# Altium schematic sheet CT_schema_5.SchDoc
size 300 x 177 mm
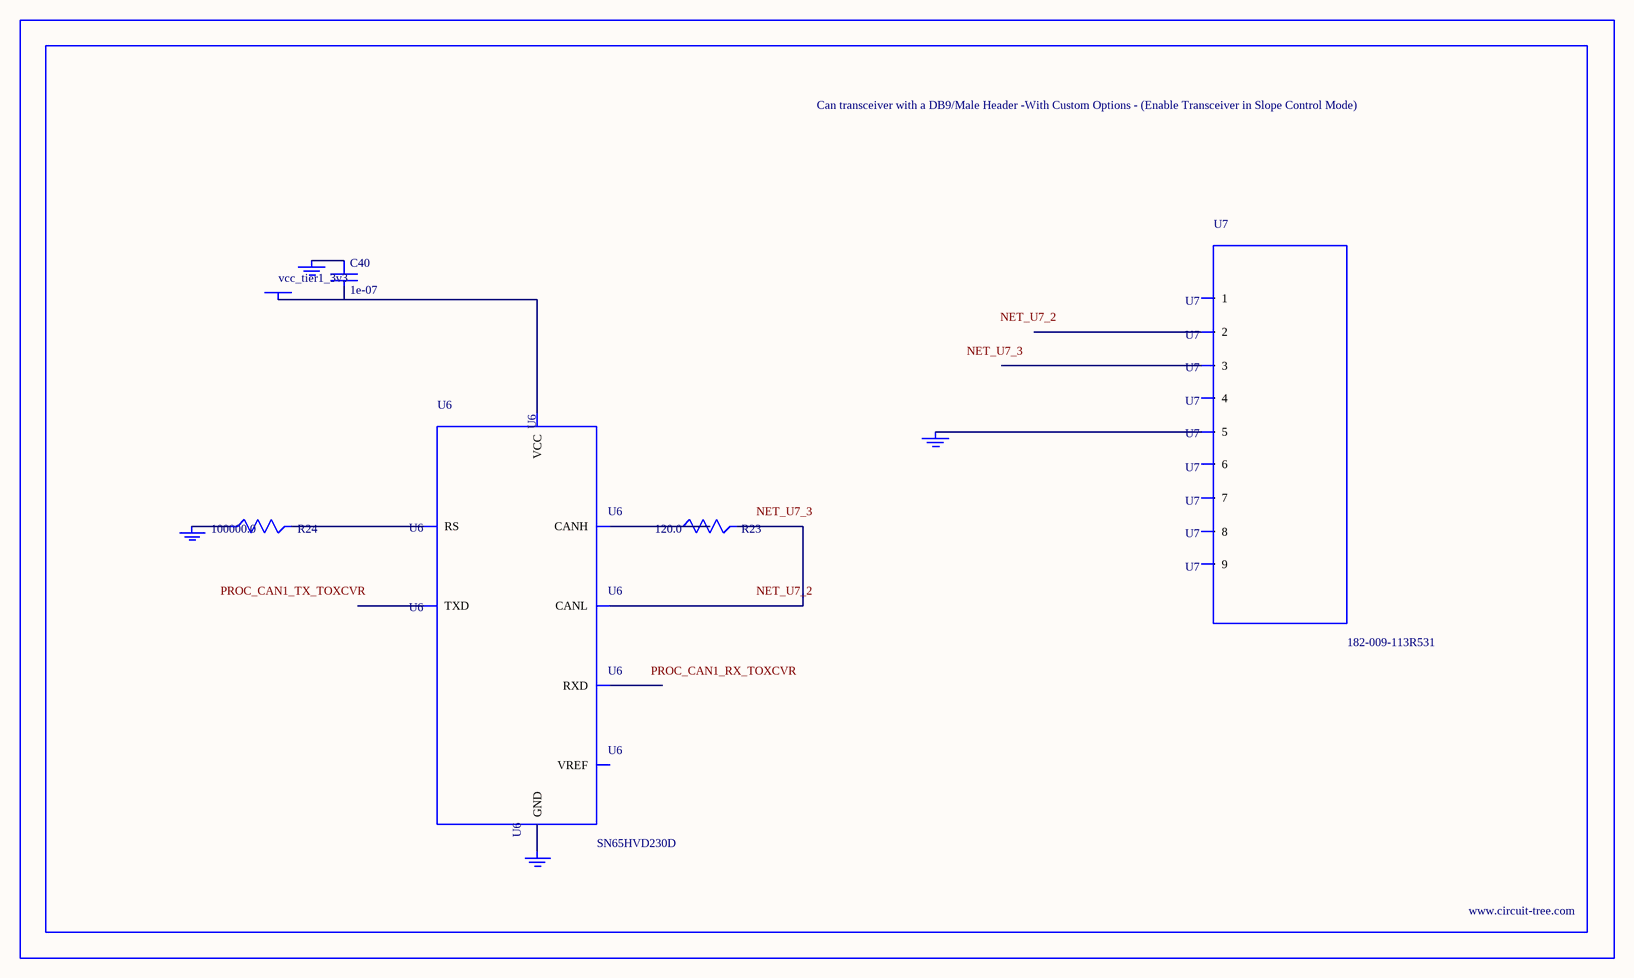
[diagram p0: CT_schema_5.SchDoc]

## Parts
BORDER4  (no value)
C40  1e-07  [C0402]
GND_INSTANCE_4_0  (no value)
GND_INSTANCE_4_1  (no value)
GND_INSTANCE_4_2  (no value)
GND_INSTANCE_4_3  (no value)
POWER_INSTANCE_4_0  vcc_tier1_3v3
R23  120.0  [R0603]
R24  100000.0  [R0603]
U6  SN65HVD230D  [SOIC-8]
U7  182-009-113R531  [182-009-MALE]

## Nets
NetC40_1: C40.1 GND_INSTANCE_4_0.0(GND)
NetC40_2: C40.2 POWER_INSTANCE_4_0.0(PWR) U6.3(VCC)
NetGND_INSTANCE_4_1_0: GND_INSTANCE_4_1.0(GND) R24.1
NetGND_INSTANCE_4_2_0: GND_INSTANCE_4_2.0(GND) U6.2(GND)
NetGND_INSTANCE_4_3_0: GND_INSTANCE_4_3.0(GND) U7.5
NetR23_1: R23.1 U6.7(CANH)
NetR23_2: R23.2 U6.6(CANL)
NetR24_2: R24.2 U6.8(RS)

Not connected (* = marked no-connect by the designer): U6 1(TXD) 4(RXD) 5(VREF); U7 1 2 3 4 6 7 8 9

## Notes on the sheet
- Labels drawn without touching a wire or pin: NET_U7_2, NET_U7_3, PROC_CAN1_RX_TOXCVR, PROC_CAN1_TX_TOXCVR

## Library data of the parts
BORDER4 = BORDER_PAGE4
C40 = C0402C104K3RACTU
GND_INSTANCE_4_0-GND_INSTANCE_4_3 = GND
POWER_INSTANCE_4_0 = PWR
R23 = RC0603JR-07120RL
R24 = RC0603JR-07100KL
